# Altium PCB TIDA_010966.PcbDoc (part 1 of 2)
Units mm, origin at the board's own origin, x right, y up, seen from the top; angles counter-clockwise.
Board outline 125.73 x 87.63 mm, 4 copper layers (Top Layer, Layer 1, Layer 2, Bottom Layer), stack 1.047 mm thick; 129 components, 41 nets, 410 pads, 452 vias.
Unrouted connection lines stored in the file: 3.
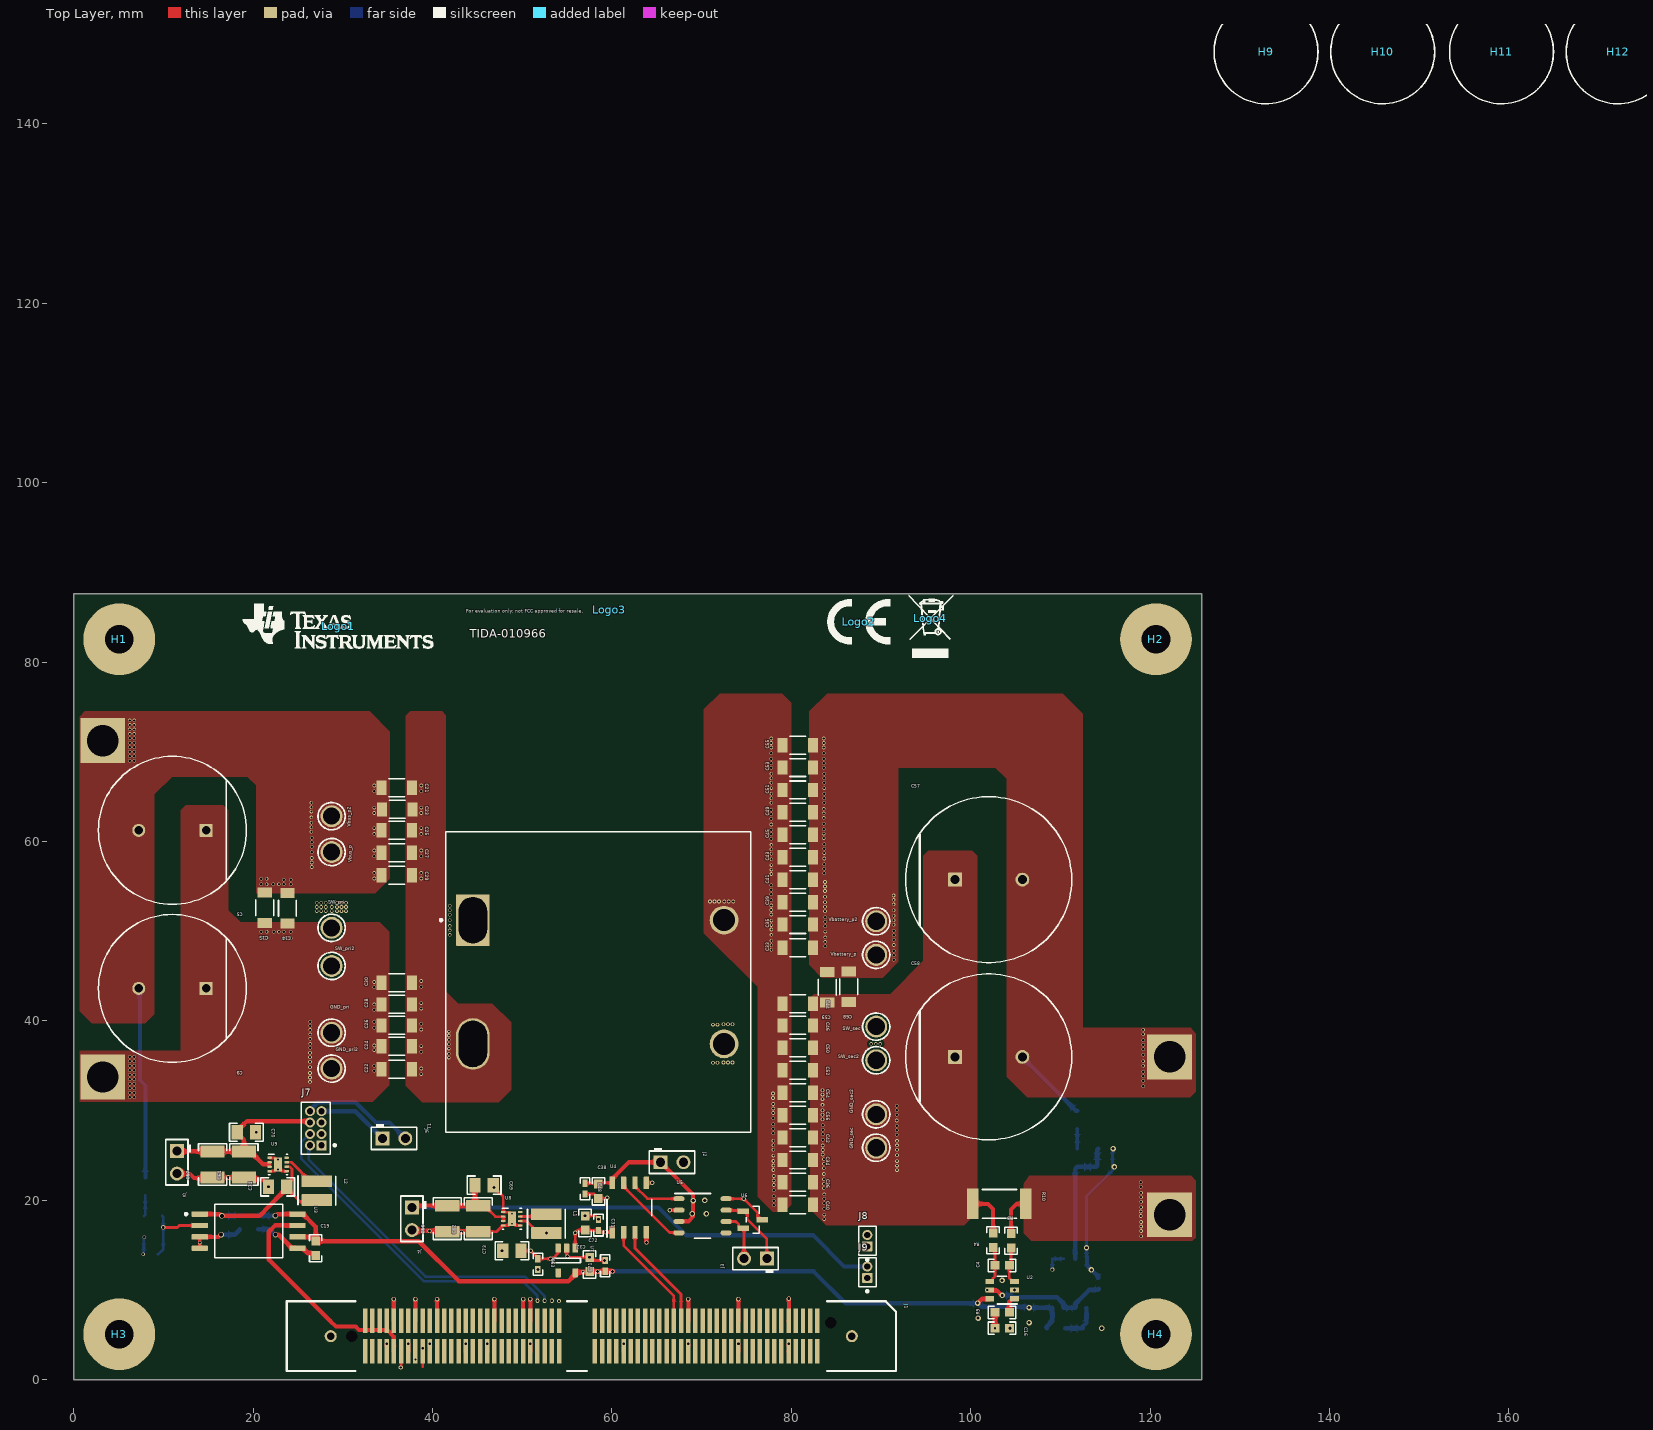
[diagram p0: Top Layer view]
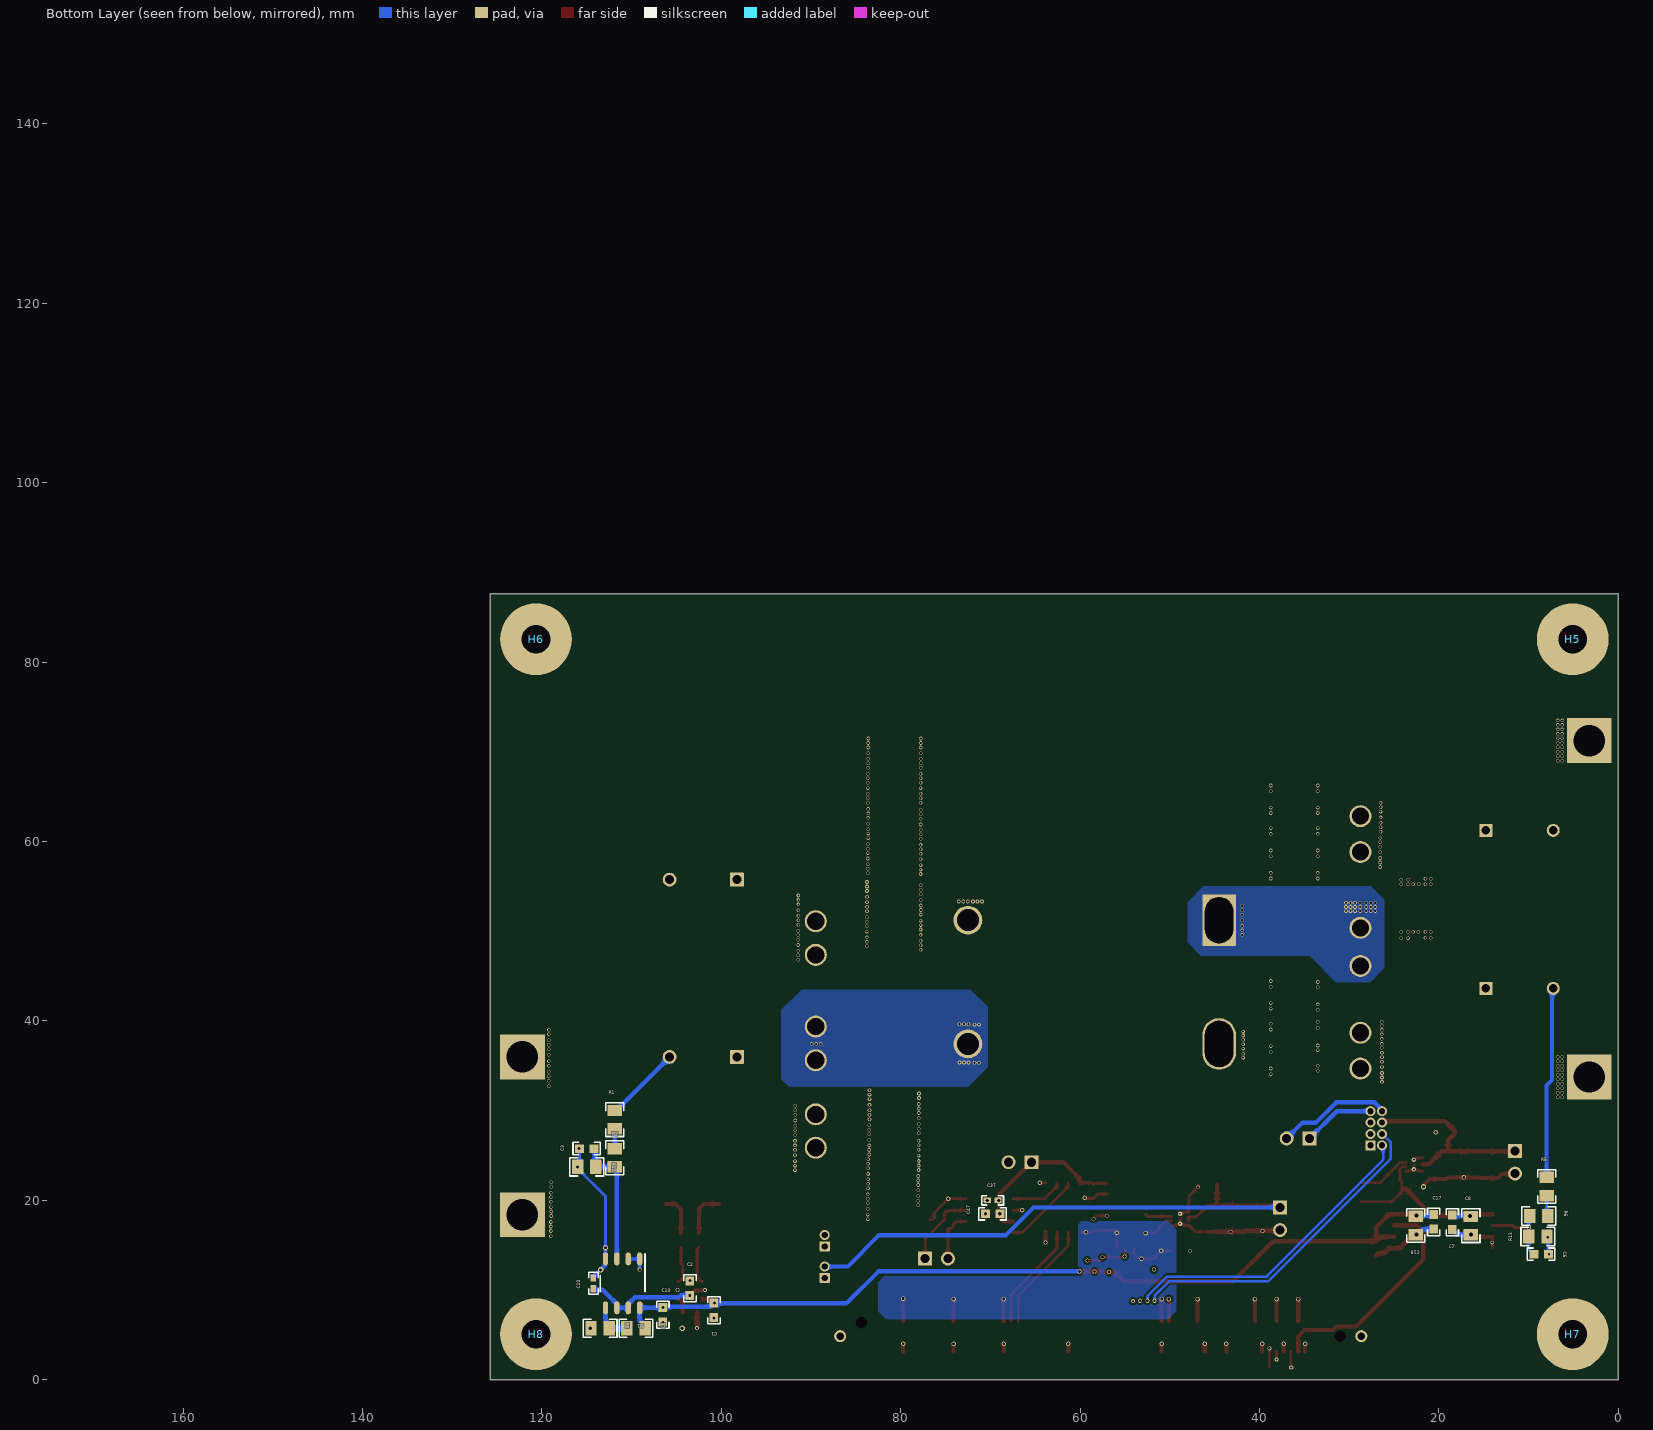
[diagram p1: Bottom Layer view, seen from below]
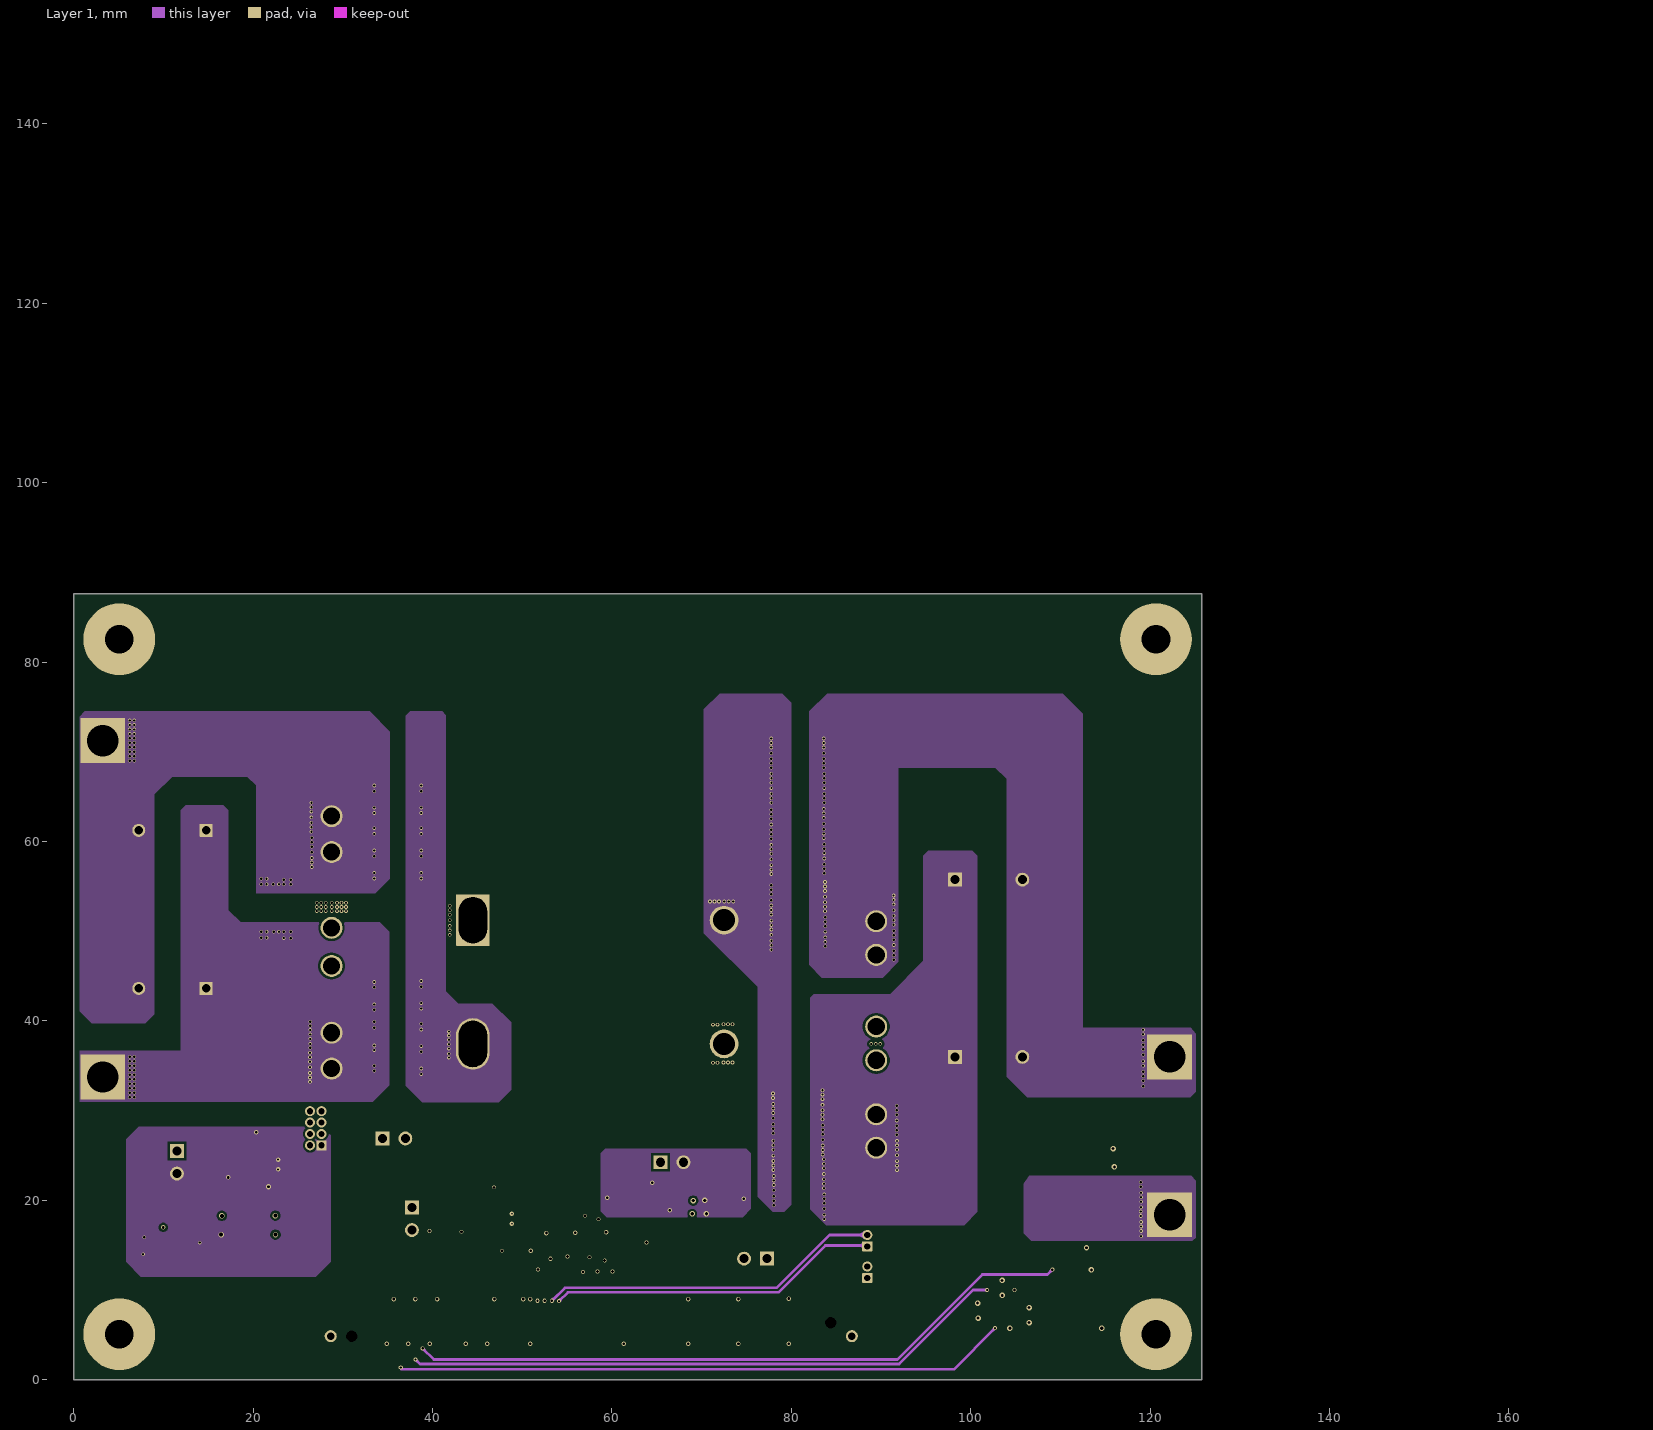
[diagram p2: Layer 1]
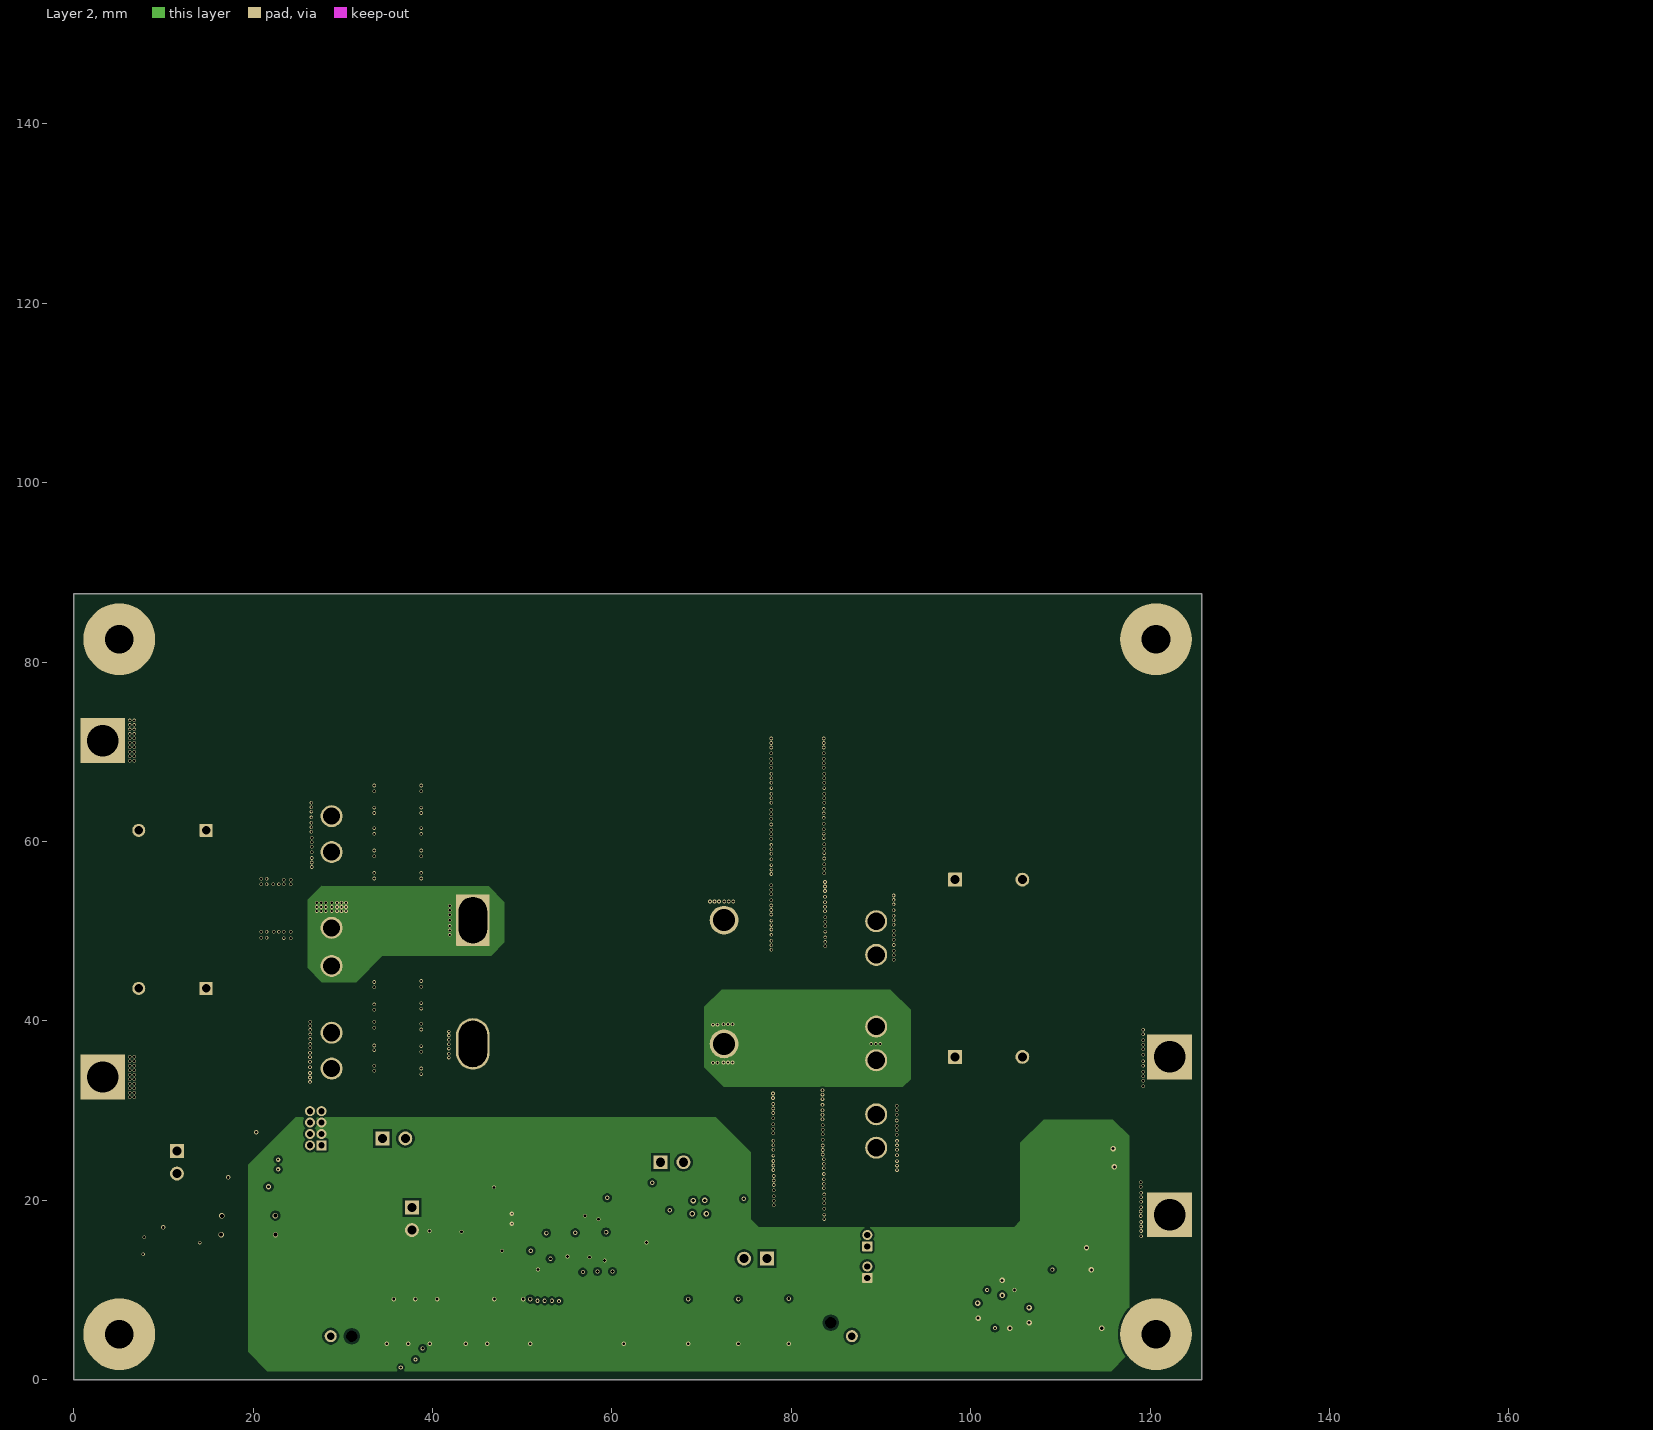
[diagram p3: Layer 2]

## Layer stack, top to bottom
Top Solder: solder mask 0.0102, Solder Resist, Dk 3.5
Top Layer: signal copper 0.07
Dielectric 1: prepreg 0.1168, PP-016, Dk 4.4
Layer 1: signal copper 0.07
Dielectric1: core 0.5334, Core-037, Dk 4.8
Layer 2: signal copper 0.07
Dielectric 2: prepreg 0.1168, PP-016, Dk 4.4
Bottom Layer: signal copper 0.07
Bottom Solder: solder mask 0.0102, Solder Resist, Dk 3.5

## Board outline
0,0 125.73,0 125.73,87.63 0,87.63

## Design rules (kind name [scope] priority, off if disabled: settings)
AcuteAngle [All] p1: minimum=4.50000000000000E+0001 checktracksonly=FALSE
AssemblyTestPointUsage [All] p1: valid=2
BoardOutlineClearance BoardOutlineClearance_MountingHoles [OnCopper and InComponentClass('Mounting Holes')] p1: gap=1 ignorepadtopadclearanceinfootprint=FALSE
BoardOutlineClearance BoardOutlineClearance_Poly [OnCopper and IsPoly] p2: gap=0.635 ignorepadtopadclearanceinfootprint=FALSE
BoardOutlineClearance [OnCopper and Not InComponentClass('Logo') and not InComponentClass('FiducialMark') and not InRegion(1000,500,4000,800) and not InPoly] p3: gap=1.016 ignorepadtopadclearanceinfootprint=FALSE
Clearance Clearance_Keepouts [((IsTrack Or IsArc) And Not InPoly) And IsFree and IsKeepOut vs ((IsTrack Or IsArc) And Not InPoly) And IsFree and IsKeepOut] p1: gap=0 ignorepadtopadclearanceinfootprint=FALSE
Clearance Clearance_Poly [InPolygon] p2: gap=0.254 ignorepadtopadclearanceinfootprint=TRUE
Clearance Clearance_FiducialMark [IsKeepOut and InComponentClass('FiducialMark') vs IsPad and InComponentClass('FiducialMark')] p3: gap=0 ignorepadtopadclearanceinfootprint=FALSE
Clearance [All] p4: gap=0.2 ignorepadtopadclearanceinfootprint=TRUE
ComponentClearance ComponentClearance_MountingHoles_FiducialMarks [InComponentClass('Mounting Holes') vs InComponentClass('FiducialMark')] p1: gap=1.27 collisioncheckmode=3 verticalgap=0.254 showdistances=FALSE
ComponentClearance ComponentClearance_Shunt [InComponentClass('Header') vs InComponentClass('Shunt')] p2: gap=0 collisioncheckmode=3 verticalgap=0 showdistances=FALSE
ComponentClearance ComponentClearance_Logo [InComponentClass('Logo')] p3: gap=0.762 collisioncheckmode=3 verticalgap=0.254 showdistances=FALSE
ComponentClearance ComponentClearance_ScrewToNut [(HasFootprint('NY PMS 440 0025 PH')) vs (HasFootprint('Keystone_1902C'))] p4: gap=0.127 collisioncheckmode=3 verticalgap=0.254 showdistances=FALSE
ComponentClearance ComponentClearance_MountingHoles [InComponentClass('Mounting Holes')] p5: gap=2.54 collisioncheckmode=3 verticalgap=2540 showdistances=FALSE
ComponentClearance ComponentClearance_SmallPassives [HasFootprint('0201*') or HasFootprint('0402*') or HasFootprint('0508') or HasFootprint('0603*') or HasFootprint('0612') or HasFootprint('0805*') or HasFootprint('0815*') or HasFootprint('0830*') or HasFootprint('1206*') or HasFootprint('1210*') or HasFootprint('1808*') or HasFootprint('1812*') or HasFootprint('1825*') or HasFootprint('2010*') or HasFootprint('2220*') or HasFootprint('2225*') or HasFootprint('2512*') or HasFootprint('2728*') or HasFootprint('3518*') vs HasFootprint('0201*') or HasFootprint('0402*') or HasFootprint('0508') or HasFootprint('0603*') or HasFootprint('0612') or HasFootprint('0805*') or HasFootprint('0815*') or HasFootprint('0830*') or HasFootprint('1206*') or HasFootprint('1210*') or HasFootprint('1808*') or HasFootprint('1812*') or HasFootprint('1825*') or HasFootprint('2010*') or HasFootprint('2220*') or HasFootprint('2225*') or HasFootprint('2512*') or HasFootprint('2728*') or HasFootprint('3518*')] p6: gap=0.38 collisioncheckmode=3 verticalgap=0.254 showdistances=FALSE
ComponentClearance ComponentClearance_THtoSMT [IsThruComponent vs IsSMTComponent] p7: gap=0.762 collisioncheckmode=3 verticalgap=0.762 showdistances=FALSE
ComponentClearance ComponentClearance_THtoTH [IsThruComponent vs IsThruComponent] p8: gap=0.508 collisioncheckmode=3 verticalgap=0.762 showdistances=FALSE
ComponentClearance [All] p9: gap=0.508 collisioncheckmode=3 verticalgap=0.254 showdistances=FALSE
DiffPairsRouting [All] p1: maxlimit=2.54 minlimit=0.254 mostfreqgap=0.254 toplayer_minwidth=0.381 toplayer_maxwidth=0.381 toplayer_prefwidth=0.381 midlayer1_minwidth=0.381 midlayer1_maxwidth=0.381 midlayer1_prefwidth=0.381 midlayer2_minwidth=0.381 midlayer2_maxwidth=0.381 midlayer2_prefwidth=0.381 bottomlayer_minwidth=0.381 bottomlayer_maxwidth=0.381 bottomlayer_prefwidth=0.381 maxuncoupledlength=25.4
FabricationTestPointUsage TestPointUsage [All] p1: valid=2 allowmultiple=FALSE
FabricationTestpoint Testpoint [All] p1: side=3 testpointundercomponent=TRUE minsize=1.016 maxsize=2.54 preferedsize=1.524 minholesize=0 maxholesize=1.016 preferedholesize=0.813 testpointgrid=0.025 allowsidetop=TRUE allowsidebottom=TRUE usegrid=TRUE gridtolerance=0
FanoutControl Fanout_LCC [IsLCC] p1: bgadir=Out bgaviamode=Centered fanoutstyle=Auto fanoutdirection=Alternating viagrid=0.025 // Fanout_LCC (Default Rule)
FanoutControl Fanout_BGA [IsBGA] p2: bgadir=Out bgaviamode=Centered fanoutstyle=Auto fanoutdirection=Alternating viagrid=0.025 // Fanout_BGA (Default Rule)
FanoutControl Fanout_Default [All] p4: bgadir=Out bgaviamode=Centered fanoutstyle=Auto fanoutdirection=Alternating viagrid=0.025 // Fanout_Default (Default Rule)
FanoutControl Fanout_Small [(CompPinCount < 5)] p5: bgadir=Out bgaviamode=Centered fanoutstyle=Auto fanoutdirection=OutThenIn viagrid=0.025 // Fanout_Small (Default Rule)
HoleSize [All] p1: absolutevalues=TRUE maxlimit=6.375 minlimit=0.2 maxpercent=80.000 minpercent=20.000
MinimumAnnularRing MinimumAnnularRing_ThermalPadVias [IsVia and InAnyComponent] p1: minimumring=0.15
MinimumAnnularRing [All] p2: minimumring=0.2
MinimumSolderMaskSliver MinimumSolderMaskSliver_Logo [InComponentClass('Logo') vs InComponentClass('Logo')] p1: minsoldermaskwidth=0.018
MinimumSolderMaskSliver [All] p2: minsoldermaskwidth=0.1
PlaneConnect [All] p1: planeconnectstyle=Relief reliefexpansion=0.254 reliefentries=4 reliefconductorwidth=0.254 reliefairgap=0.254
PolygonConnect [All] p1: connectstyle=Direct reliefconductorwidth=0.254 reliefentries=4 polygonreliefangle="90 Angle" airgapwidth=0.254
RoutingVias ThermalPadVias [IsVia and InAnyComponent] p1: holewidth=0.2 width=0.5 viastyle="Through Hole" minholewidth=0.2 minwidth=0.5 maxholewidth=0.33 maxwidth=0.6
RoutingVias [All] p2: holewidth=0.406 width=0.864 viastyle="Through Hole" minholewidth=0.2 minwidth=0.61 maxholewidth=10.16 maxwidth=16.51
SilkToBoardRegionClearance [Not ((IsComment or IsDesignator) And (Hide <> 'False')) and not InRegion(1000,500,4000,800)] p1:
SilkToSilkClearance SilkToSilkClearance_Pb-FreeLogo [(HasFootprint('Pb-Free_Overlay_Medium') OR HasFootprint('Pb-Free_Overlay_Small')) vs (HasFootprint('Pb-Free_Overlay_Medium') OR HasFootprint('Pb-Free_Overlay_Small'))] p1: silktosilkclearance=0
SilkToSilkClearance [All] p2: silktosilkclearance=0.1
SilkToSolderMaskClearance SilkToComponentPadClearance [(IsPad or IsFill or IsRegion) and InAnycomponent] p1: minsilkscreentomaskgap=0.127 clearancetoexposedcopper=TRUE
SilkToSolderMaskClearance "Silk to Solder Mask Opening" [All] p2: minsilkscreentomaskgap=0.1 clearancetoexposedcopper=FALSE
SolderMaskExpansion [All] p1: expansion=0.05 istentingtop=FALSE
UnRoutedNet [All] p1: checkbadconnections=TRUE
Width [All] p1: maxlimit=2.54 minlimit=0.152 preferedwidth=0.254 checkconnectedcopper=TRUE
14 further rules are at their usual default settings.

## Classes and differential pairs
component class "Mounting Holes": H1 H2 H3 H4
component class Logo: Logo1
component class TIDA_010966_Hardware: H1 H2 H3 H4 H5 H6 H7 H8 H9 H10 H11 H12 Logo1 Logo2 Logo3 Logo4
component class TIDA_010966_BlankSheet: C1 C2 C3 C4 C5 C6 C7 C8 C9 C10 C14 C15 C16 C17 C18 C19 C20 C21 C22 C23 C24 C25 C26 C27 C28 C29 C30 C31 C32 C33 C34 C35 C36 C37 C38 C39 C40 C41 C42 C43 C44 C45 C46 C47 C48 C49 C50 C51 C52 C53 C54 C55 C56 C57 C58 C59 C62 C63 C64 C66 C67 C68 C69 C70 C71 C72 C73 C74 GND_pri GND_pri2 GND_sec GND_sec2 J1 J2 J3 J4 J5 J6 J7 J8 J9 L1 L2 R1 R2 R3 R4 R5 R6 R7 R8 R9 R10 R11 R12 SW_pri SW_pri2 SW_sec SW_sec2 T1 U1 U2 U3 U4 U5 U6 U7 U8 U9 Vbattery_p Vbattery_p2 Vbus_p Vbus_p2

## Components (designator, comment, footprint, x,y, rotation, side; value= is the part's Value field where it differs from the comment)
C1 "CGA3E2X7R1E104K080AA" 0603 100.815,7.752 r270 bottom value=0.1uF
C2 "GRM1885C1H301JA01D" 0603 103.494,10.202 r90 bottom value=300pF
C3 "GRM1885C1H222JA01D" 0603 115,25.766 r0 bottom value=2200pF
C4 "GRM1885C1H222JA01D" 0603 103.494,12.75 r180 top value=2200pF
C5 "EGPD800ELL102ML35H" FP-EGPD800ELL102ML35H_RADIAL-MFG 11,61.25 r180 top value=1mF
C6 "0603ZC101KAT2A" 0603 8.604,13.995 r180 bottom value=100pF
C7 "GRM1885C1H301JA01D" 0603 18.5,17.558 r270 bottom value=300pF
C8 "C0805C105K3RACTU" 0805_HV 16.432,17.184 r90 bottom value=1uF
C9 "EGPD800ELL102ML35H" FP-EGPD800ELL102ML35H_RADIAL-MFG 11,43.627 r180 top value=1mF
C10 "GRM188R71C104KA01D" 0603 106.511,7.25 r90 bottom value=0.1uF
C14 "CGA5L3X7S2A225K160AB" 1206_180 23.827,52.579 r270 top value=2.2uF
C15 "CGA5L3X7S2A225K160AB" 1206_180 21.301,52.615 r270 top value=2.2uF
C16 "GRM1885C1H301JA01D" 0603 103.494,5.75 r0 top value=300pF
C17 "GRM1885C1H301JA01D" 0603 20.575,17.599 r90 bottom value=300pF
C18 "C0805C105K3RACTU" 0805_HV 22.575,17.199 r270 bottom value=1uF
C19 "GRM1885C1H301JA01D" 0603 26.98,14.659 r90 top value=300pF
C20 "C1005X5R1A104K050BA" 0402 114.25,10.75 r90 bottom value=0.1uF
C21 "C3216C0G2A104J160AC" 1206_190 36,66 r0 top value=0.1uF
C22 "C3216C0G2A104J160AC" 1206_190 36,34.623 r180 top value=0.1uF
C23 "C3216C0G2A104J160AC" 1206_190 36.048,63.577 r0 top value=0.1uF
C24 "C3216C0G2A104J160AC" 1206_190 36,37.177 r180 top value=0.1uF
C25 "C3216C0G2A104J160AC" 1206_190 36,61.25 r0 top value=0.1uF
C26 "C3216C0G2A104J160AC" 1206_190 36,39.5 r180 top value=0.1uF
C27 "C3216C0G2A104J160AC" 1206_190 36,58.75 r0 top value=0.1uF
C28 "C3216C0G2A104J160AC" 1206_190 36,41.841 r180 top value=0.1uF
C29 "C3216C0G2A104J160AC" 1206_190 36,56.25 r0 top value=0.1uF
C30 "C3216C0G2A104J160AC" 1206_190 36,44.25 r180 top value=0.1uF
C31 "0402YC104KAT2A" 0402 58.5,17.25 r270 top value=0.1uF
C32 "GRM188Z71C475KE21D" 0603 57,17.478 r270 top value=4.7uF
C33 "C3216C0G2A104J160AC" 1206_190 80.714,48.173 r180 top value=0.1uF
C34 "C3216C0G2A104J160AC" 1206_190 80.714,24.5 r0 top value=0.1uF
C35 "C3216C0G2A104J160AC" 1206_190 80.714,50.75 r180 top value=0.1uF
C36 "C3216C0G2A104J160AC" 1206_190 80.714,22 r0 top value=0.1uF
C37 "0402YC104KAT2A" 0402 69.75,20 r180 bottom value=0.1uF
C38 "GRM188Z71C475KE21D" 0603 58.5,21.003 r90 top value=4.7uF
C39 "C3216C0G2A104J160AC" 1206_190 80.714,53.25 r180 top value=0.1uF
C40 "C3216C0G2A104J160AC" 1206_190 80.714,19.5 r0 top value=0.1uF
C41 "C3216C0G2A104J160AC" 1206_190 80.714,55.75 r180 top value=0.1uF
C42 "C3216C0G2A104J160AC" 1206_190 80.714,27 r0 top value=0.1uF
C43 "C3216C0G2A104J160AC" 1206_190 80.714,58.25 r180 top value=0.1uF
C44 "C3216C0G2A104J160AC" 1206_190 80.714,41.905 r0 top value=0.1uF
C45 "C3216C0G2A104J160AC" 1206_190 80.714,60.75 r180 top value=0.1uF
C46 "C3216C0G2A104J160AC" 1206_190 80.714,39.5 r0 top value=0.1uF
C47 "GRM188Z71C475KE21D" 0603 69.75,18.502 r0 bottom value=4.7uF
C48 "0402YC104KAT2A" 0402 57,21.303 r270 top value=0.1uF
C49 "C3216C0G2A104J160AC" 1206_190 80.714,63.25 r180 top value=0.1uF
C50 "C3216C0G2A104J160AC" 1206_190 80.714,37 r0 top value=0.1uF
C51 "C3216C0G2A104J160AC" 1206_190 80.714,65.75 r180 top value=0.1uF
C52 "C3216C0G2A104J160AC" 1206_190 80.714,34.5 r0 top value=0.1uF
C53 "C3216C0G2A104J160AC" 1206_190 80.714,68.25 r180 top value=0.1uF
C54 "C3216C0G2A104J160AC" 1206_190 80.714,32 r0 top value=0.1uF
C55 "C3216C0G2A104J160AC" 1206_190 80.714,70.75 r180 top value=0.1uF
C56 "C3216C0G2A104J160AC" 1206_190 80.714,29.5 r0 top value=0.1uF
C57 "EY3A102MNN1850M" FP-EY3A102MNN1850M_RADIAL-MFG 102,55.75 r0 top value=1mF
C58 "EY3A102MNN1850M" FP-EY3A102MNN1850M_RADIAL-MFG 102,36 r0 top value=1mF
C59 "CGA5L3X7S2A225K160AB" 1206_180 84,43.75 r270 top value=2.2uF
C62 "GRM32ER61C476KE15L" 1210_270 45.1,17.952 r90 top value=47uF
C63 "CGA2B3X7R1E104K050BB" 0402 51.75,12.882 r270 top value=0.1uF
C64 "GRM32ER61C476KE15L" 1210_270 18.98,24 r90 top value=47uF
C66 "GRM32ER61C476KE15L" 1210_270 41.641,17.952 r90 top value=47uF
C67 "GRM32ER61C476KE15L" 1210_270 15.48,24 r90 top value=47uF
C68 "CGA5L3X7S2A225K160AB" 1206_180 86.411,43.804 r270 top value=2.2uF
C69 "C0805C105K3RACTU" 0805_HV 45.75,21.702 r0 top value=1uF
C70 "C0805C105K3RACTU" 0805_HV 19.25,27.589 r0 top value=1uF
C71 "C1005X5R1A104K050BA" 0402 59.25,12.702 r90 top value=0.1uF
C72 "GRM188R71A105KA61D" 0603 57.5,12.852 r90 top value=1uF
C73 "CL21A226KOQNNNE" 0805_HV 48.85,14.376 r180 top value=22uF
C74 "CL21A226KOQNNNE" 0805_HV 22.73,21.5 r180 top value=22uF
GND_pri "0312-0-15-15-34-27-10-0" Mill-Max_0312-0-15-15-34-27-10-0 28.75,38.687 r90 top
GND_pri2 "0312-0-15-15-34-27-10-0" Mill-Max_0312-0-15-15-34-27-10-0 28.75,34.687 r90 top
GND_sec "0312-0-15-15-34-27-10-0" Mill-Max_0312-0-15-15-34-27-10-0 89.464,25.867 r180 top
GND_sec2 "0312-0-15-15-34-27-10-0" Mill-Max_0312-0-15-15-34-27-10-0 89.464,29.592 r180 top
H1 "NY PMS 440 0025 PH" "NY PMS 440 0025 PH" 5.08,82.55 r0 top locked
H2 "NY PMS 440 0025 PH" "NY PMS 440 0025 PH" 120.65,82.55 r0 top locked
H3 "NY PMS 440 0025 PH" "NY PMS 440 0025 PH" 5.08,5.08 r0 top locked
H4 "NY PMS 440 0025 PH" "NY PMS 440 0025 PH" 120.65,5.08 r0 top locked
H5 "1902C" Keystone_1902C 5.08,82.55 r180 bottom locked
H6 "1902C" Keystone_1902C 120.65,82.55 r180 bottom locked
H7 "1902C" Keystone_1902C 5.08,5.08 r180 bottom locked
H8 "1902C" Keystone_1902C 120.65,5.08 r180 bottom locked
H9 "SJ-5303 (CLEAR)" Bumpon_SJ5003Transparent 132.923,148.036 r0 top
H10 "SJ-5303 (CLEAR)" Bumpon_SJ5003Transparent 145.923,148.036 r0 top
H11 "SJ-5303 (CLEAR)" Bumpon_SJ5003Transparent 159.173,148.036 r0 top
H12 "SJ-5303 (CLEAR)" Bumpon_SJ5003Transparent 172.173,148.036 r0 top
J1 "HSEC8-160-01-L-DV-A-BL" controlCARD-120HSEC 55.857,4.835 r0 top
J2 "HTSW-102-09-G-S" Samtec_HTSW-102-09-x-S 66.7,24.25 r0 top
J3 "HTSW-102-09-G-S" Samtec_HTSW-102-09-x-S 76,13.5 r180 top
J4 "HTSW-102-09-G-S" Samtec_HTSW-102-09-x-S 37.7,17.952 r270 top
J5 "HTSW-102-09-G-S" Samtec_HTSW-102-09-x-S 11.5,24.25 r270 top
J6 "HTSW-102-09-G-S" Samtec_HTSW-102-09-x-S 35.7,26.903 r0 top
J7 "M50-3000445" FP-M50-3000445_CONN_SCKT_STRP8-MFG 26.984,28.037 r90 top
J8 "M50-3030242" FP-M50-3030242_HDR2-MFG 88.464,15.502 r90 top
J9 "M50-3030242" FP-M50-3030242_HDR2-MFG 88.464,11.982 r90 top
L1 "74438336022" FP-74438336010_SMD2-MFG 52.7,17.402 r270 top
L2 "74438336022" FP-74438336010_SMD2-MFG 27.109,21.097 r270 top
Logo1 "Texas Instruments" TI_Stacked_Overlay_Small 29.475,84 r0 top
Logo2 "CE Mark" CE_Mark_5mm 87.5,84.5 r0 top
Logo3 "FCC disclaimer" FCC_disclaimer 59.69,85.852 r0 top
Logo4 "WEEE logo" WEEE_Minimum 95.5,84.87 r0 top
R1 "RT0805BRD0750K5L" 0805_HV 111.875,29 r90 bottom value=50.5k
R2 "RT0805BRD0750K5L" 0805_HV 111.875,24.75 r90 bottom value=50.5k
R3 "RNCF0603AKT10R0" 0603 104.494,15.5 r270 top value=10.0
R4 "RNCF0603AKT10R0" 0603 102.494,15.55 r270 top value=10.0
R5 "RT0805BRD0750K5L" 0805_HV 7.979,21.548 r90 bottom value=50.5k
R6 "RT0805BRD0750K5L" 0805_HV 8.859,18.255 r180 bottom value=50.5k
R7 "PLTT0805Z1002QGT5" 0805_HV 109.5,5.75 r180 bottom value=10.0k
R8 "PLTT0805Z1002QGT5" 0805_HV 113.5,5.75 r180 bottom value=10.0k
R9 "RC0603FR-0751RL" 0603 103.494,7.5 r180 top value=51.0
R10 "LRMAP2512-R01FT4" 2512 103.187,19.6 r0 top value=0.01
R11 "RT0805BRD075K3L" 0805_HV 8.963,15.964 r0 bottom value=5.30k
R12 "RG2012P-362-B-T5" 0805_HV 115,23.734 r180 bottom value=3.60k
SW_pri "0312-0-15-15-34-27-10-0" Mill-Max_0312-0-15-15-34-27-10-0 28.75,50.382 r0 top
SW_pri2 "0312-0-15-15-34-27-10-0" Mill-Max_0312-0-15-15-34-27-10-0 28.75,46.132 r90 top
SW_sec "0312-0-15-15-34-27-10-0" Mill-Max_0312-0-15-15-34-27-10-0 89.464,35.618 r0 top
SW_sec2 "0312-0-15-15-34-27-10-0" Mill-Max_0312-0-15-15-34-27-10-0 89.464,39.367 r90 top
T1 "TIDA-010966-transformer" FP-PMP41134_transformer_PTH-MFG 58.5,44.339 r90 top
U1 "TLV9062IDR" D0008A_N 111,10.75 r270 bottom
U2 "INA181A1IDBVR" DBV0006A_N 103.494,10 r180 top
U3 "AMC0311RDWV" DWV0008A-MFG 19.5,16.564 r0 top
U4 "ISO7721DR" D0008B_HV 61.935,19.203 r90 top
U5 "TCAN1042HDRQ1" D0008A_L 70.1,18.278 r0 top
U6 "ESD2CAN24DBZR" DBZ0003A-MFG 75.7,17.85 r0 top
U7 "TLV71333PQDBVRQ1" DBV0005A_N 54.95,13.302 r270 top
U8 "TPS62163DSGR" DSG0008A 48.85,17.952 r0 top
U9 "TPS62163DSGR" DSG0008A 22.78,24 r0 top
Vbattery_p "0312-0-15-15-34-27-10-0" Mill-Max_0312-0-15-15-34-27-10-0 89.464,47.367 r90 top
Vbattery_p2 "0312-0-15-15-34-27-10-0" Mill-Max_0312-0-15-15-34-27-10-0 89.464,51.117 r90 top
Vbus_p "0312-0-15-15-34-27-10-0" Mill-Max_0312-0-15-15-34-27-10-0 28.75,58.827 r90 top
Vbus_p2 "0312-0-15-15-34-27-10-0" Mill-Max_0312-0-15-15-34-27-10-0 28.75,62.827 r180 top

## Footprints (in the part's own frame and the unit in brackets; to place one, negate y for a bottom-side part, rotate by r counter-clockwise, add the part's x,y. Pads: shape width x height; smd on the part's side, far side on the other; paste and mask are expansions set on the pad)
0402 [mm] "0402 from SM-752 data"
  rect 0.8x0.6 smd: 1(-0.6,0) 2(0.6,0)
  silkscreen extent -1.22,-0.52 1.22,0.52, body extent -0.55,-0.3 0.55,0.3, height 0.6
0603 [mm] "0603 from SM-752 data"
  rect 1x0.95 smd: 1(-0.8,0) 2(0.8,0)
  silkscreen extent -1.52,-0.69 1.52,0.69, body extent -0.87,-0.47 0.87,0.47, height 1
0805_HV [mil] "0805 with 30mil clearance between pads"
  rect 50x63 smd: 1(-40,0) 2(40,0)
  silkscreen extent -74,-40 74,40, body extent -43,-29 43,29, height 57
1206_180 [mm] "1206_180"
  rect 1.1x1.6 smd: 1(-1.7,0) 2(1.7,0)
  silkscreen extent -0.9,-1 0.9,1, body extent -1.75,-0.95 1.75,0.95, height 1.8
1206_190 [mm] "1206_190"
  rect 1.1x1.6 smd: 1(-1.7,0) 2(1.7,0)
  silkscreen extent -0.9,-1 0.9,1, body extent -1.75,-0.95 1.75,0.95, height 1.9
1210_270 [mm] "1210"
  rect 1.3x2.7 smd: 1(-1.45,0) 2(1.45,0)
  silkscreen extent -2.32,-1.57 2.32,1.57, body extent -1.7,-1.35 1.7,1.35, height 2.7
2512 [mm] "Chip Resistor, Body 6.3x3.2mm, IPC Medium Density"
  rect 1.3x3.4 smd: 1(-2.95,0) 2(2.95,0)
  silkscreen extent -1.9,-1.6 1.9,1.6, body extent -3.22,-1.67 3.22,1.67, height 0.71
Bumpon_SJ5003Transparent [mil] "3M Hemispherical Bumpon transparent"
  round 1 on Mech3: 0(0,0)
  silkscreen extent -228,-228 228,228, body extent -217,-218 219,218, height 197
CE_Mark_5mm [mm] "Minimum text height for CE Mark"
  silkscreen extent -3.5,-2.5 3.5,2.5
controlCARD-120HSEC [mm] "Pads are not numbered according to Samtec datasheet."
  rect 0.5x2.724 smd: 1(-23.357,-1.678) 2(-23.357,1.722) 3(-22.557,-1.678) 4(-22.557,1.722) 5(-21.757,-1.678) 6(-21.757,1.722) 7(-20.957,-1.678) 8(-20.957,1.722) 9(-20.157,-1.678) 10(-20.157,1.722) 11(-19.357,-1.678) 12(-19.357,1.722) 13(-18.557,-1.678) 14(-18.557,1.722) 15(-17.757,-1.678) 16(-17.757,1.722) 17(-16.957,-1.678) 18(-16.957,1.722) 19(-16.157,-1.678) 20(-16.157,1.722) 21(-15.357,-1.678) 22(-15.357,1.722) 23(-14.557,-1.678) 24(-14.557,1.722) 25(-13.757,-1.678) 26(-13.757,1.722) 27(-12.957,-1.678) 28(-12.957,1.722) 29(-12.157,-1.678) 30(-12.157,1.722) 31(-11.357,-1.678) 32(-11.357,1.722) 33(-10.557,-1.678) 34(-10.557,1.722) 35(-9.757,-1.678) 36(-9.757,1.722) 37(-8.957,-1.678) 38(-8.957,1.722) 39(-8.157,-1.678) 40(-8.157,1.722) 41(-7.357,-1.678) 42(-7.357,1.722) 43(-6.557,-1.678) 44(-6.557,1.722) 45(-5.757,-1.678) 46(-5.757,1.722) 47(-4.957,-1.678) 48(-4.957,1.722) 49(-4.157,-1.678) 50(-4.157,1.722) 51(-3.357,-1.678) 52(-3.357,1.722) 53(-2.557,-1.678) 54(-2.557,1.722) 55(-1.757,-1.678) 56(-1.757,1.722) 57(2.243,-1.678) 58(2.243,1.722) 59(3.043,-1.678) 60(3.043,1.722) 61(3.843,-1.678) 62(3.843,1.722) 63(4.643,-1.678) 64(4.643,1.722) 65(5.443,-1.678) 66(5.443,1.722) 67(6.243,-1.678) 68(6.243,1.722) 69(7.043,-1.678) 70(7.043,1.722) 71(7.843,-1.678) 72(7.843,1.722) 73(8.643,-1.678) 74(8.643,1.722) 75(9.443,-1.678) 76(9.443,1.722) 77(10.243,-1.678) 78(10.243,1.722) 79(11.043,-1.678) 80(11.043,1.722) 81(11.843,-1.678) 82(11.843,1.722) 83(12.643,-1.678) 84(12.643,1.722) 85(13.443,-1.678) 86(13.443,1.722) 87(14.243,-1.678) 88(14.243,1.722) 89(15.043,-1.678) 90(15.043,1.722) 91(15.843,-1.678) 92(15.843,1.722) 93(16.643,-1.678) 94(16.643,1.722) 95(17.443,-1.678) 96(17.443,1.722) 97(18.243,-1.678) 98(18.243,1.722) 99(19.043,-1.678) 100(19.043,1.722) 101(19.843,-1.678) 102(19.843,1.722) 103(20.643,-1.678) 104(20.643,1.722) 105(21.443,-1.678) 106(21.443,1.722) 107(22.243,-1.678) 108(22.243,1.722) 109(23.043,-1.678) 110(23.043,1.722) 111(23.843,-1.678) 112(23.843,1.722) 113(24.643,-1.678) 114(24.643,1.722) 115(25.443,-1.678) 116(25.443,1.722) 117(26.243,-1.678) 118(26.243,1.722) 119(27.043,-1.678) 120(27.043,1.722)
  round 0.025 hole 1.27 unplated mask+0.876: 181(-24.857,0.022) 182(28.543,1.522)
  round 1.348 hole 0.84: 185(-27.207,0.022) 186(30.893,0.022)
  silkscreen extent -32.11,-3.86 35.8,3.9, body extent -31.75,-3.48 35.3,3.52, height 12.35
D0008A_L [mm] "SOIC, 8-Leads, Body 4.9x3.9mm, Pitch 1.27mm, IPC High Density"
  oval 1.25x0.55 smd: 1(-2.625,1.905) 2(-2.625,0.635) 3(-2.625,-0.635) 4(-2.625,-1.905) 5(2.625,-1.905) 6(2.625,-0.635) 7(2.625,0.635) 8(2.625,1.905)
  silkscreen extent -3.1,-2.5 0.9,2.5, body extent -3,-2.45 3,2.45, height 1.63
D0008A_N [mm] "SOIC, 8-Leads, Body 4.9x3.9mm, Pitch 1.27mm, IPC Medium Density"
  oval 1.45x0.6 smd: 1(-2.725,1.905) 2(-2.725,0.635) 3(-2.725,-0.635) 4(-2.725,-1.905) 5(2.725,-1.905) 6(2.725,-0.635) 7(2.725,0.635) 8(2.725,1.905)
  silkscreen extent -3.3,-2.5 0.9,2.5, body extent -3,-2.45 3,2.45, height 1.63
D0008B_HV [mm] "SOIC, 8-Leads, Body 4.9x3.9mm, Pitch 1.27mm, HV / Isolation option"
  rrect17% 1.4x0.6 smd: 1(-2.75,1.905) 2(-2.75,0.635) 3(-2.75,-0.635) 4(-2.75,-1.905) 5(2.75,-1.905) 6(2.75,-0.635) 7(2.75,0.635) 8(2.75,1.905)
  silkscreen extent -3.3,-2.5 0.9,2.5, body extent -3,-2.45 3,2.45, height 1.63
DBV0005A_N [mm] "SOT23, 5-Leads, Body 2.9x1.6mm, Pitch 0.95mm, Lead Span 2.8mm, IPC Medium Density"
  rrect17% 1x0.6 smd: 1(-1.375,0.95) 2(-1.375,0) 3(-1.375,-0.95) 4(1.375,-0.95) 5(1.375,0.95)
  silkscreen extent -0.25,-1.55 0.25,1.55, body extent -1.42,-1.46 1.42,1.46, height 1.09
DBV0006A_N [mm] "SOT23, 6-Leads, Body 2.9x1.6mm, Pitch 0.95mm, Lead Span 2.8mm, IPC Medium Density"
  rrect17% 1x0.6 smd: 1(-1.375,0.95) 2(-1.375,0) 3(-1.375,-0.95) 4(1.375,-0.95) 5(1.375,0) 6(1.375,0.95)
  silkscreen extent -1.68,-1.55 0.5,1.55, body extent -1.42,-1.46 1.42,1.46, height 1.12
DBZ0003A-MFG [mm]
  rrect17% 1.3x0.6 smd paste+0 mask+0: 1(-1.05,0.95) 2(-1.05,-0.95) 3(1.05,0)
  silkscreen extent -0.7,-1.52 0.7,1.52, body extent -1.8,-1.62 1.8,1.62, height 0.25
DSG0008A [mm] "SON, 8-Leads, Body 2x2mm, Pitch 0.5mm, Thermal Pad 1.6x0.9mm, TI Recommended"
  rrect40% 0.5x0.25 smd: 1(-0.95,0.75) 2(-0.95,0.25) 3(-0.95,-0.25) 4(-0.95,-0.75) 5(0.95,-0.75) 6(0.95,-0.25) 7(0.95,0.25) 8(0.95,0.75)
  rrect14% 0.9x0.7 on Top Paste: 9(0,-0.45) 9(0,0.45)
  rrect11% 0.9x1.6 smd paste-0.45: 9(0,0)
  silkscreen extent -1.07,-1.15 1.07,1.15, body extent -1,-1 1,1, height 0.77
DWV0008A-MFG [mm] "Recommended Land Pattern"
  rrect17% 1.8x0.6 smd paste+0 mask+0: 1(-5.45,1.905) 2(-5.45,0.635) 3(-5.45,-0.635) 4(-5.45,-1.905) 5(5.45,-1.905) 6(5.45,-0.635) 7(5.45,0.635) 8(5.45,1.905)
  silkscreen extent -7.1,-2.98 3.8,2.98, body extent -6.45,-3.22 6.45,3.22, height 0.25
FCC_disclaimer [mm]
FP-74438336010_SMD2-MFG [mm]
  rrect8% 1.3x3.4 smd paste+0 mask+0: 1(-1.05,0) 2(1.05,0)
  silkscreen extent -1.6,-2.1 1.6,2.1, body extent -1.8,-1.8 1.8,1.8, height 0.25
FP-EGPD800ELL102ML35H_RADIAL-MFG [mm]
  rrect7% 1.45x1.45 hole 0.95 paste-1000 mask+0: 1(-3.75,0)
  round 1.45 hole 0.95 paste-1000 mask+0: 2(3.75,0)
  silkscreen extent -8.25,-8.25 8.25,8.25, body extent -8.35,-8.35 8.35,8.35, height 0.25
FP-EY3A102MNN1850M_RADIAL-MFG [mm]
  rrect6% 1.55x1.55 hole 1 paste-1000 mask+0: 1(-3.75,0)
  round 1.55 hole 1 paste-1000 mask+0: 2(3.75,0)
  silkscreen extent -9.25,-9.25 9.25,9.25, body extent -9.35,-9.35 9.35,9.35, height 0.25
FP-M50-3000445_CONN_SCKT_STRP8-MFG [mm]
  rrect9% 1.12x1.12 hole 0.7 paste-1000 mask+0: 1(-1.905,-0.635)
  round 1.12 hole 0.7 paste-1000 mask+0: 2(-1.905,0.635) 3(-0.635,-0.635) 4(-0.635,0.635) 5(0.635,-0.635) 6(0.635,0.635) 7(1.905,-0.635) 8(1.905,0.635)
  silkscreen extent -2.89,-2.24 2.89,1.63, body extent -2.99,-1.73 2.99,1.73, height 0.25
FP-M50-3030242_HDR2-MFG [mm]
  rrect9% 1.12x1.12 hole 0.7 paste-1000 mask+0: 1(-0.635,0)
  round 1.12 hole 0.7 paste-1000 mask+0: 2(0.635,0)
  silkscreen extent -2.25,-0.97 1.62,0.97, body extent -1.72,-1.07 1.72,1.07, height 0.25
FP-PMP41134_transformer_PTH-MFG [mm]
  rrect4% 5.75x3.75 hole 3.15 slot 5.15 at 0 deg paste-2539.97 mask+0: 1(6.9,14)
  rrect100% 5.75x3.75 hole 3.15 slot 5.15 at 0 deg paste-2539.97 mask+0: 2(-6.9,14)
  round 3.2 hole 2.45 paste-2539.97 mask+0: 3(-6.9,-14) 4(6.9,-14)
  silkscreen extent -16.75,-17 16.75,17.67, body extent -16.85,-17.1 16.85,17.1, height 0.25
Keystone_1902C [mil] "Hex Standoff, 4-40 threaded, nylon"
  round 1 on Mech4: 0(0,0)
  body extent -145,-126 146,126, height 501
Mill-Max_0312-0-15-15-34-27-10-0 [mm] "Pin Receptacle, .032-.046\" .075\" Dia, Gold, TH"
  round 2.45 hole 1.905: 1(0,0)
  silkscreen extent -1.52,-1.52 1.52,1.52, body extent -1.15,-1.15 1.16,1.15, height 0.46
"NY PMS 440 0025 PH" [mm] "4-40 nylon screw and mounting hole"
  round 8 hole 3.2: 1(0,0)
  body extent -3.3,-3.3 3.3,3.3, height 2.69
Samtec_HTSW-102-09-x-S [mm] "Header, 2x1, 2.54mm, TH"
  rect 1.55x1.55 hole 1.02: 1(-1.27,0)
  round 1.55 hole 1.02: 2(1.27,0)
  silkscreen extent -2.54,-1.24 2.54,1.6, body extent -2.54,-1.24 2.54,1.24, height 8.38
TI_Stacked_Overlay_Small [mm]
  silkscreen extent -10.63,-2.49 10.63,2.49
WEEE_Minimum [mm] "WEEElie bin"
  silkscreen extent -2.42,-4.38 2.52,2.65

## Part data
C1: library part CMP-0007077-5, "CAP, CERM, 0.1 uF, 25 V, +/- 10%, X7R, AEC-Q200 Grade 1, 0603", Cap_Case=0603, Manufacturer=TDK, Supplier Part Number 1=445-5667-1-ND, TempCo=X7R, Tolerance_%=10%, Value1=Unknown, Value2=25V, ValueDisplayed=0.1uF
C2 C7 C17 C19: library part CMP-0007206-4, "CAP, CERM, 300 pF, 50 V, +/- 5%, C0G/NP0, 0603", Cap_Case=0603, Manufacturer=MuRata, Supplier Part Number 1=490-1438-1-ND, TempCo=C0G/NP0, Tolerance_%=5%, Value1=Unknown, Value2=50V, ValueDisplayed=100nF
C3 C4: library part CMP-0007198-4, "CAP, CERM, 2200 pF, 50 V, +/- 5%, C0G/NP0, 0603", Cap_Case=0603, Manufacturer=MuRata, Supplier Part Number 1=490-1459-1-ND, TempCo=C0G/NP0, Tolerance_%=5%, Value1=Unknown, Value2=50V, ValueDisplayed=2200pF
C5 C9: library part CMP-0097417-1, "1000 µF 80 V Aluminum Electrolytic Capacitors Radial, Can 27mOhm @ 100kHz 2000 Hrs @ 135°C", Digikey Part Number=565-EGPD800ELL102ML35H-ND, Leakage Current=2400uA, Manufacturer="United Chemi-Con", Mouser Part Number=661-EGPD800E102ML35H, Operating Temperature Range="-40°C to +135°C", Tolerance_%=20%, ValueDisplayed=1000uF
C6: library part CMP-0006812-4, "CAP, CERM, 100 pF, 10 V, +/- 10%, X7R, 0603", Cap_Case=0603, Manufacturer=AVX, Supplier Part Number 1=0603ZC101KAT2A-ND, TempCo=X7R, Tolerance_%=10%, Value1=Unknown, Value2=10V, ValueDisplayed=100pF
C8 C18 C69 C70: library part CMP-0007728-2, "CAP, CERM, 1 uF, 25 V, +/- 10%, X7R, 0805", Cap_Case=0805, Manufacturer=Kemet, Supplier Part Number 1=399-8004-1-ND, TempCo=X7R, Tolerance_%=10%, Value1=Unknown, Value2=25V, ValueDisplayed=1uF
C10: library part CMP-0007378-5, "CAP, CERM, 0.1 uF, 16 V, +/- 10%, X7R, 0603", Cap_Case=0603, Manufacturer=MuRata, Supplier Part Number 1=490-1532-1-ND, TempCo=X7R, Tolerance_%=10%, Value1=Unknown, Value2=16V, ValueDisplayed=0.1uF
C14 C15 C59 C68: library part CMP-0008790-2, "CAP, CERM, 2.2 uF, 100 V, +/- 10%, X7S, AEC-Q200 Grade 1, 1206", Cap_Case=1206_180, Manufacturer=TDK, Supplier Part Number 1=445-6994-1-ND, TempCo=X7S, Tolerance_%=10%, Value1="0.005718 ohm", Value2=100V, ValueDisplayed=2.2uF
C16: library part CMP-0007206-4, "CAP, CERM, 300 pF, 50 V, +/- 5%, C0G/NP0, 0603", Cap_Case=0603, Manufacturer=MuRata, Supplier Part Number 1=490-1438-1-ND, TempCo=C0G/NP0, Tolerance_%=5%, Value1=Unknown, Value2=50V, ValueDisplayed=300pF
C20 C71: library part CMP-0006259-2, "CAP, CERM, 0.1 uF, 10 V, +/- 10%, X5R, 0402", Cap_Case=0402, Manufacturer=TDK, Supplier Part Number 1=445-1265-1-ND, TempCo=X5R, Tolerance_%=10%, Value1=Unknown, Value2=10V, ValueDisplayed=0.1uF
C21 C22 C23 C24 C25 C26 C27 C28 C29 C30 C33 C34 C35 C36 C39 C40 C41 C42 C43 C44 C45 C46 C49 C50 C51 C52 C53 C54 C55 C56: library part CMP-0008643-2, "CAP, CERM, 0.1 uF, 100 V, +/- 5%, C0G/NP0, 1206_190", Cap_Case=1206, Manufacturer=TDK, Supplier Part Number 1=445-172677-6-ND, TempCo=C0G/NP0, Tolerance_%=5%, Value1=Unknown, Value2=100V, ValueDisplayed=0.1uF
C31 C37 C48: library part CMP-0006201-2, "CAP, CERM, 0.1 uF, 16 V, +/- 10%, X7R, 0402", Cap_Case=0402, Manufacturer=AVX, Supplier Part Number 1=478-7888-1-ND, TempCo=X7R, Tolerance_%=10%, Value1=Unknown, Value2=16V, ValueDisplayed=0.1uF
C32 C38 C47: library part CMP-0064936-4, "CAP, CERM, 4.7 uF, 16 V,+/- 10%, X7R, 0603", Cap_Case=0603, Manufacturer=MuRata, TempCo=X7R, Tolerance_%=10%, Value1=Unknown, Value2=16V, ValueDisplayed=4.7uF
C57 C58: library part CMP-0122297-1, "1000 µF 120 V Aluminum Electrolytic Capacitors Radial, Can 10000 Hrs @ 105°C", Digikey Part Number=4191-EY3A102MNN1850M-ND, Leakage Current=1200uA, Manufacturer=Chinsan, Operating Temperature Range="-55°C to +105°C", Tolerance_%=20%, ValueDisplayed=1000uF
C62 C64 C66 C67: library part CMP-0009211-2, "CAP, CERM, 47 uF, 16 V, +/- 10%, X5R, 1210", Cap_Case=1210, Manufacturer=MuRata, Supplier Part Number 1=GRM32ER61C476KE15L-ND, TempCo=X5R, Tolerance_%=10%, Value1=Unknown, Value2=16V, ValueDisplayed=47uF
C63: library part CMP-0080610-1, "CAP, CERM, 0.1 µF, 25 V,+/- 10%, X7R, AEC-Q200 Grade 1, 0402", Cap_Case=0402, Manufacturer=TDK, Supplier Part Number 1=445-6902-1-ND, TempCo=X7R, Tolerance_%=10%, Value2=25V, ValueDisplayed=0.1µF
C72: library part CMP-0007365-1, "CAP, CERM, 1 uF, 10 V, +/- 10%, X7R, 0603", Cap_Case=0603, Manufacturer=MuRata, Supplier Part Number 1=490-3899-1-ND, TempCo=X7R, Tolerance_%=10%, Value1="0.011 ohm", Value2=10V, ValueDisplayed=1uF
C73 C74: library part CMP-0085852-1, "CAP, CERM, 22 µF, 16 V,+/- 10%, X5R, 0805", Cap_Case=0805, Manufacturer="Samsung Electro-Mechanics", TempCo=X5R, Tolerance_%=10%, Value2=16V, ValueDisplayed=22µF
GND_pri GND_pri2 GND_sec GND_sec2 SW_pri SW_pri2 SW_sec SW_sec2 Vbattery_p Vbattery_p2 Vbus_p Vbus_p2: library part CMP-0055026-1, Manufacturer=Mill-Max, Supplier Part Number 1=0312-015153427100-ND
H1 H2 H3 H4: library part CMP-0003617-1, "Machine Screw, Round, #4-40 x 1/4, Nylon, Philips panhead", Manufacturer="B&F Fastener Supply", Supplier Part Number 1=H542-ND
H5 H6 H7 H8: library part CMP-0003610-1, "Standoff, Hex, 0.5\"L #4-40 Nylon", Manufacturer=Keystone, Supplier Part Number 1=36-1902C-ND
H9 H10 H11 H12: library part CMP-0003620-1, "Bumpon, Hemisphere, 0.44 X 0.20, Clear", Manufacturer=3M, Supplier Part Number 1=SJ5303-7-ND
J1: library part CMP-0003814-2, "C2000 controlCARD-120HSEC connector, SMT", Manufacturer=Samtec
J2 J3 J4 J5 J6: library part CMP-0075626-1, "Header, 100mil, 2x1, Gold, TH", Color=Black, Manufacturer=Samtec
J7: library part CMP-0097755-1, "Conn Socket Strip SKT 8 POS 1.27mm Solder ST Thru-Hole", Current_A=1A, Manufacturer=Harwin, Operating Temperature Range="-40°C to +105°C"
J8 J9: library part CMP-0097274-1, "2 Position Receptacle Connector 0.050\" (1.27mm) Through Hole Gold", Current_A=1A, Digikey Part Number=952-3574-ND, Manufacturer=Harwin, Mouser Part Number=855-M50-3030242, Operating Temperature Range="-40°C to +105°C"
L1 L2: library part CMP-0087867-1, "2.2µH Shielded Molded Inductor 2.4A 67mOhm Max 2-SMD", Manufacturer="Wurth Electronics"
Logo1: library part CMP-0074838-1, "Texas Instrument Corporate Signature"
Logo2: library part CMP-0074844-1
Logo3: library part CMP-0074847-1, "FCC_disclaimer"
Logo4: library part CMP-0074769-1
R1 R2 R5 R6: library part CMP-0020148-1, "RES, 50.5 k, 0.1%, 0.125 W, 0805", Manufacturer="Yageo America", Power_W=125mW, TempCo="25 ppm/C", Tolerance_%=0.1%, Value2=0.125W, Value_Code=50k5, ValueDisplayed=50.5k
R3 R4: library part CMP-0023625-2, "RES, 10.0, 0.05%, 0.1 W, 0603", Manufacturer="Stackpole Electronics Inc", Power_W=100mW, Supplier Part Number 1=RNCF0603AKT10R0CT-ND, TempCo="10 ppm/C", Tolerance_%=0.05%, Value2=0.1W, Value_Code=10R0, ValueDisplayed=10.0
R7 R8: library part CMP-0018847-1, "RES, 10.0 k, 0.02%, 0.25 W, 0805", Manufacturer=Vishay-Dale, Power_W=250mW, Supplier Part Number 1=PLTT10.0KACT-ND, TempCo="5 ppm/C", Tolerance_%=0.02%, Value2=0.25W, Value_Code=10k0, ValueDisplayed=10.0k
R9: library part CMP-0023169-5, "RES, 51.0, 1%, 0.1 W, 0603", Manufacturer=Yageo, Power_W=100mW, Supplier Part Number 1=311-51.0HRCT-ND, TempCo="100 ppm/C", Tolerance_%=1%, Value2=0.1W, Value_Code=51R0, ValueDisplayed=51.0
R10: library part CMP-0078925-1, "RES, 0.01, 1%, 3 W, AEC-Q200 Grade 0, 2512", Manufacturer="TT Electronics/IRC", Power_W=3W, Supplier Part Number 1=985-1559-1-ND, TempCo="50 ppm/C", Tolerance_%=1%, Value_Code=R010, ValueDisplayed=0.01
R11: library part CMP-0020211-1, "RES, 5.30 k, 0.1%, 0.125 W, 0805", Manufacturer="Yageo America", Power_W=125mW, Supplier Part Number 1=9982965, TempCo="25 ppm/C", Tolerance_%=0.1%, Value2=0.125W, Value_Code=5k30, ValueDisplayed=5.30k
R12: library part CMP-0018966-2, "RES, 3.60 k, 0.1%, 0.125 W, 0805", Manufacturer="Susumu Co Ltd", Power_W=125mW, Supplier Part Number 1=RG20P3.6KBCT-ND, TempCo="25 ppm/C", Tolerance_%=0.1%, Value2=0.125W, Value_Code=3k60, ValueDisplayed=3.60k
T1: library part CMP-0123505-1, "TRANSFORMER", Manufacturer=3L, Operating Temperature Range=to, Part Number=PMP41134_transformer
U1: library part CMP-0013007-4, "10-MHz, Low-Noise, RRIO, CMOS Operational Amplifier for Cost-Sensitive Systems, D0008A (SOIC-8)", Alternate Manufacturer="Texas Instruments", Alternate PartNumber=TLV9062ID, Operating Temperature Range="-40 to 125 C", Rating=Catalog
U2: library part CMP-0013230-2, "Bidirectional, Low- and High-Side Measurement, Multichannel, Voltage Output, Current-Sense Amplifier, DBV0006A (SOT-6)", Alternate Manufacturer="Texas Instruments", Alternate PartNumber=INA181A1IDBVT
U3: library part CMP-0124048-1, "Precision, 2.25V Input, Basic and Reinforced Isolated Amplifiers With Single-Ended, Ratiometric Output", Input Bias Current=3.5nA, Input Offset Voltage=0.2mV, Manufacturer="Texas Instruments", Max Supply Voltage=5.5V, Min Supply Voltage=3V, Operating Temperature Range="-40°C to +125°C", Output Current Per Channel=14mA
U4: library part CMP-0076059-2, "High Speed, Robust EMC Dual-Channel Digital Isolator, D0008B (SOIC-8)", Alternate Manufacturer="Texas Instruments", Alternate PartNumber=ISO7721D, Operating Temperature Range="-55 to 125 C", Rating=Catalog
U5: library part CMP-0075990-1, "Automotive Fault Protected CAN Transceiver With Flexible Data-Rate, D0008A (SOIC-8)", Alternate Manufacturer="Texas Instruments", Alternate PartNumber=TCAN1042HDQ1
U6: library part CMP-0093261-1, "24-V, 2-Channel ESD Protection Diode for In-Vehicle Networks", Breakdown Voltage=25.5V, Clamping Voltage=32V, Manufacturer="Texas Instruments", Operating Temperature Range="-55°C to +150°C", ValueDisplayed=3pF
U7: library part CMP-0073750-1, "Capacitor-Free, 150-mA, LDO Regulator w/ Foldback Current Limit, DBV0005A (SOT-23-5)", Alternate Manufacturer="Texas Instruments"
U8 U9: library part CMP-0037791-2, "Buck Step Down Regulator with 3 to 17 V Input and 5 V Output, -40 to 85 degC, 8-Pin WSON (DSG), Green (RoHS & no Sb/Br)", Manufacturer="Texas Instruments", Rating=Catalog, Switch Current Limit(Typ)(A)=1.8

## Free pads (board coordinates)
  rect 5x5 hole 3.5: 2(3.228,33.75) 2(3.228,71.25) 2(122.174,18.4) 2(122.174,36)

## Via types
v1: diameter 0.4, hole 0.254, Top Layer to Bottom Layer, tented both sides, 371 vias
v2: diameter 0.5, hole 0.3, Top Layer to Bottom Layer, tented both sides, 31 vias
v3: diameter 0.61, hole 0.35, Top Layer to Bottom Layer, tented both sides, 14 vias
v4: diameter 0.43, hole 0.32, Top Layer to Bottom Layer, tented both sides, 12 vias
v5: diameter 0.45, hole 0.254, Top Layer to Bottom Layer, tented both sides, 5 vias
v6: diameter 0.45, hole 0.26, Top Layer to Bottom Layer, tented both sides, 4 vias
v7: diameter 0.61, hole 0.45, Top Layer to Bottom Layer, tented both sides, 4 vias
v8: diameter 0.5, hole 0.2, Top Layer to Bottom Layer, 4 vias
v9: diameter 0.45, hole 0.33, Top Layer to Bottom Layer, tented both sides, 3 vias
v10: diameter 0.61, hole 0.3, Top Layer to Bottom Layer, tented both sides, 3 vias
v11: diameter 0.45, hole 0.25, Top Layer to Bottom Layer, tented both sides, 1 vias

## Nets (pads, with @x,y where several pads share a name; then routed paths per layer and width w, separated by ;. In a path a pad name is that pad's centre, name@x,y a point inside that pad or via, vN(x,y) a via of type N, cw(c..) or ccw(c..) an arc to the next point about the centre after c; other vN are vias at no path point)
1.65V_sec: C2.1 C20.1 J1.15 U1.6 U1.7 U2.5 | length 82.6
  Top Layer w0.3: v5(38.1,2.25) J1.15@38.1,3.157
  Top Layer w0.5: U2.5@102.119,10 102.169,9.95 102.917,9.95 103.465,9.402 v10(103.494,9.402)
  Layer 1 w0.3: v5(38.1,2.25) 38.6,1.75 92.021,1.75 100.271,10 v5(101.831,10)
  Bottom Layer w0.45: U1.7@110.365,8.025 U1.6@111.635,8.025
  Bottom Layer w0.5: v10(103.494,9.402) 104.527,9.402 104.729,9.2 109.615,9.2 110.365,8.45 U1.7@110.365,8.025 ; U1.6@111.635,8.025 111.635,8.45 113.2,10.015 114.2,10.015 114.25,10.065 C20.1@114.25,10.15
3.3V_sec: C1.1 C10.2 C17.2 C18.1 C19.2 C71.1 C72.1 R7.2 U1.8 U2.6 U3.6 U3.8 U7.5 | length 101.3
  Top Layer w0.5: v7(22.491,18.299) 22.521,18.299 22.691,18.469 U3.8@24.95,18.469 25.55,18.469 26.98,17.039 C19.2@26.98,15.484 ; U3.6@24.95,15.929 26.535,15.929 C19.2@26.98,15.484 ; v9@60.164,12.102 C71.1@59.25,12.102 59.225,12.077 v9(58.375,12.077) 57.525,12.077 C72.1@57.5,12.052 57.438,11.99 v9(56.75,11.99) 55.95,11.99 55.9,11.94 U7.5@55.9,11.927 55.85,11.877 55.85,11.677 55.15,10.977 42.947,10.977 38.467,15.457 26.982,15.457 C19.2@26.98,15.459 C19.2@26.98,15.484 ; v3(100.755,8.554) 100.785,8.554 101.231,9 102.069,9 U2.6@102.119,9.05
  Bottom Layer w0.5: C17.2@20.575,18.399 20.667,18.307 22.483,18.307 v7(22.491,18.299) C18.1@22.575,18.215 ; v9(60.063,12.077) 82.478,12.077 86.051,8.504 100.705,8.504 v3(100.755,8.554) ; C1.1@100.98,8.329 101.173,8.136 106.424,8.136 106.523,8.037 109.082,8.037 U1.8@109.095,8.025 109.095,6.526 108.484,5.915 R7.2@108.484,5.75 R7.2@108.398,5.836
  other v3: 106.511,8.05
5V_ISO: C37.2 C38.2 C47.1 C48.1 J2.1 U4.8 U5.3 | length 19.4
  Top Layer w0.3: C48.1@57,21.903 58.4,21.903 C38.2@58.5,21.803 58.65,21.953 U4.8@60.03,21.953
  Top Layer w0.45: U4.8@60.03,21.953 60.03,22.353 61.927,24.25 J2.1@65.43,24.25 69.05,20.63 69.05,18.202 68.51,17.662 67.494,17.662 U5.3@67.475,17.643 U5.3@67.825,17.643
  other v3: 68.95,18.502 69.057,19.98
5V_pri: C7.1 C8.2 C74.1 L2.2 U3.1 U9.6 | length 21.6
  Top Layer w0.3: U9.6@23.73,23.75 24.071,23.75 24.33,23.491 24.33,22.249 24.125,22.044 24.125,21.251 C74.1@23.83,21.251 ; C74.1@23.746,21.335 C74.1@23.83,21.251 ; L2.2@28.65,19.848 25.233,19.848 C74.1@23.83,21.251
  Top Layer w0.5: U3.1@14.05,18.469 v7@16.291,18.469 ; v7(16.511,18.279) 20.754,18.279 21.268,18.793 21.268,18.856 C74.1@23.746,21.335
  Bottom Layer w0.5: v7(16.511,18.279) 18.421,18.279 C7.1@18.5,18.358
5V_sec: C31.2 C32.2 C63.1 C73.1 J1.48 J1.84 J1.98 J1.112 L1.2 U4.1 U7.1 U7.3 U8.6 | length 24.9
  Top Layer w0.3: U8.6@49.8,17.702 50.5,17.702 51.15,17.052 51.15,16.852 51.65,16.352 v2(52.7,16.352) ; C73.1@49.866,14.376 v2(50.955,14.376) 51.75,13.582 C63.1@51.75,13.482 53.361,13.482 53.983,14.103 53.983,14.66 U7.3@54,14.677 ; U7.1@55.9,14.677 v2(55.9,16.377) 56.201,16.678 C32.2@57,16.678 57.028,16.65 C31.2@58.5,16.65 58.5,16.603 58.65,16.453 U4.1@60.03,16.453
  Top Layer w0.45: J1.48@50.9,6.557 v2(50.9,9) ; J1.84@68.5,6.557 68.51,6.567 v2(68.51,9) ; J1.98@74.1,6.557 v2(74.1,9) ; J1.112@79.7,6.557 79.714,6.571 v2(79.714,9.05)
  other v2: 53.15,13.482 59.34,16.453
+12V_sec: C62.2 C66.2 C69.1 J4.1 J9.2 U8.2 U8.3 | length 67.2
  Top Layer w0.3: C62.2@45.1,19.402 45.8,19.402 47.025,18.177 47.9,18.177 U8.3@47.9,17.702
  Top Layer w0.45: J4.1@37.7,19.222 37.88,19.402 C66.2@41.641,19.402
  Top Layer w0.5: C66.2@41.641,19.402 C62.2@45.1,19.402 44.734,19.768 C69.1@44.734,21.702
  Bottom Layer w0.45: J4.1@37.7,19.222 65.168,19.222 68.28,16.111 82.389,16.111 85.883,12.617 J9.2@88.464,12.617
+15V_pri: C64.2 C67.2 C70.1 J5.1 J7.6 U9.2 U9.3 | length 22.2
  Top Layer w0.5: J5.1@11.5,25.52 11.57,25.45 C67.2@15.48,25.45 C64.2@18.98,25.45 ; 21.804,24 21.13,24 19.68,25.45 C64.2@18.98,25.45 ; J7.6@26.349,28.672 26.181,28.672 26.015,28.839 19.319,28.839 18.234,27.754 C70.1@18.234,27.589 18.234,27.423 18.619,27.038 18.687,27.038 18.98,26.746 C64.2@18.98,25.45
+15V_pri_SW: J6.1 J7.7 | length 8.1
  Bottom Layer w0.5: J7.7@27.619,29.942 31.39,29.942 J6.1@34.43,26.903
CS: C16.1 J1.11 R9.2 | length 71.7
  Top Layer w0.3: v5(36.455,1.357) 36.5,1.402 J1.11@36.5,3.157
  Top Layer w0.5: v5(102.694,5.75) R9.2@102.694,7.5
  Layer 1 w0.3: v5@36.5,1.166 98.11,1.166 v5(102.694,5.75)
GND_ISO: C37.1 C38.1 C47.2 C48.2 J2.2 U4.5 U5.2 U5.8 U6.3 | length 9.8
  Top Layer w0.3: C48.2@57,20.703 58.025,20.703 58.5,20.228 C38.1@58.5,20.203 59.41,20.203 v2(59.485,20.278) ; U4.5@63.84,21.953 v2(64.5,21.953) ; v2(66.432,18.913) U5.2@67.475,18.913 ; U5.8@72.725,20.183 v2(74.682,20.183) 76.265,18.6 76.265,18 76.415,17.85 U6.3@76.75,17.85
  Bottom Layer w0.45: v3(70.525,18.502) C47.2@70.55,18.502
  other v3: 70.35,20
